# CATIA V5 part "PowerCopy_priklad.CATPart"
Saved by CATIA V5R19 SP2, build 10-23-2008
Part number: Part2
Bounding box of the stored display mesh (mm): x -30 to 30, y -30 to 30, z 0 to 130
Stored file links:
  D:\Catia\PowerCopy_priklad.CATPart
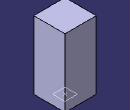
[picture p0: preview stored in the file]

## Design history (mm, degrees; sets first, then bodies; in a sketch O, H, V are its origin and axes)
Set1
  Point1 "Stred profilu": stored without definition
  Plane1 "Zakladna": stored without definition
Body1 (main body)
  Sketch1 on Plane1, origin (0, 0, 0), H (1, 0, 0), V (0, 1, 0)
    line L1 (-30, 30) -> (30, 30)
    line L2 (30, 30) -> (30, -30)
    line L3 (30, -30) -> (-30, -30)
    line L4 (-30, -30) -> (-30, 30)
    horizontal: L1 H, L3 H
    vertical: L2 V, L4 V
  Pad1: profile Sketch1, direction (0, 0, 1), length 130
